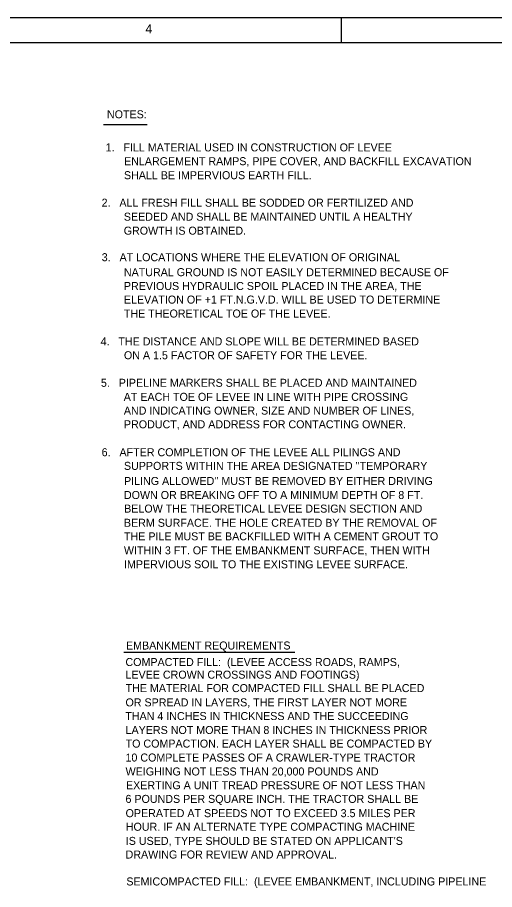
# Model space of a CAD drawing. Extents: x 2127959 to 2137375, y 2146193 to 2153470.
# Drawn here: x 2133592 to 2135661, y 2149692 to 2153470 of the extents above; entities that cross this region are included whole.
import ezdxf

# ---------------------------------------------------------------- set-up
doc = ezdxf.new("R2010")
doc.units = 0
doc.layers.add('Level 1', color=7, linetype='Continuous')

msp = doc.modelspace()

# ---------------------------------------------------------------- linework, layer by layer
at = {"layer": 'Level 1'}
for p, q in [((2134996.845, 2153362.032), (2134996.862, 2153469.881)), ((2128280.166, 2153362.032), (2136678.794, 2153362.027)), ((2133964.481, 2153005.766), (2134154.593, 2153005.766)), ((2134053.658, 2150720.428), (2134795.212, 2150720.428))]:
    msp.add_line(p, q, dxfattribs=at)
msp.add_lwpolyline([(2127959.193, 2153469.025), (2137374.681, 2153469.025), (2137374.681, 2146193.484), (2127959.193, 2146193.484)], close=True, dxfattribs=at)

# ---------------------------------------------------------------- texts
for s, height, p in [('4', 40.073, (2134146.898, 2153400.552)), ('NOTES:', 34.657, (2133980.147, 2153033.079)), ('1.   FILL MATERIAL USED IN CONSTRUCTION OF LEVEE', 34.657, (2133974.327, 2152889.634)), ('ENLARGEMENT RAMPS, PIPE COVER, AND BACKFILL EXCAVATION', 34.657, (2134054.237, 2152829.902)), ('SHALL BE IMPERVIOUS EARTH FILL.', 34.657, (2134053.827, 2152769.252)), ('2.   ALL FRESH FILL SHALL BE SODDED OR FERTILIZED AND', 34.657, (2133956.84, 2152650.108)), ('SEEDED AND SHALL BE MAINTAINED UNTIL A HEALTHY ', 34.657, (2134053.412, 2152589.45)), ('GROWTH IS OBTAINED.', 34.657, (2134052.897, 2152528.985)), ('3.   AT LOCATIONS WHERE THE ELEVATION OF ORIGINAL', 34.657, (2133957.525, 2152414.021)), ('NATURAL GROUND IS NOT EASILY DETERMINED BECAUSE OF', 34.657, (2134053.567, 2152349.091)), ('PREVIOUS HYDRAULIC SPOIL PLACED IN THE AREA, THE ', 34.657, (2134053.618, 2152289.237)), ('ELEVATION OF +1 FT.N.G.V.D. WILL BE USED TO DETERMINE', 34.657, (2134053.633, 2152230.438)), ('THE THEORETICAL TOE OF THE LEVEE.', 34.657, (2134053.182, 2152169.988)), ('4.   THE DISTANCE AND SLOPE WILL BE DETERMINED BASED ', 34.657, (2133952.512, 2152049.325)), ('ON A 1.5 FACTOR OF SAFETY FOR THE LEVEE.', 34.657, (2134053.766, 2151989.3)), ('5.   PIPELINE MARKERS SHALL BE PLACED AND MAINTAINED', 34.657, (2133953.984, 2151870.078)), ('AT EACH TOE OF LEVEE IN LINE WITH PIPE CROSSING', 34.657, (2134052.765, 2151809.183)), ('AND INDICATING OWNER, SIZE AND NUMBER OF LINES,', 34.657, (2134053.344, 2151749.548)), ('PRODUCT, AND ADDRESS FOR CONTACTING OWNER.', 34.657, (2134053.693, 2151690.26)), ('6.   AFTER COMPLETION OF THE LEVEE ALL PILINGS AND', 34.657, (2133957.166, 2151569.249)), ("SUPPORTS WITHIN THE AREA DESIGNATED ''TEMPORARY ", 34.657, (2134053.74, 2151510.22)), ("PILING ALLOWED'' MUST BE REMOVED BY EITHER DRIVING ", 34.657, (2134054.163, 2151444.733)), ('DOWN OR BREAKING OFF TO A MINIMUM DEPTH OF 8 FT.', 34.657, (2134053.764, 2151384.025)), ('BELOW THE THEORETICAL LEVEE DESIGN SECTION AND', 34.657, (2134054.66, 2151325.11)), ('BERM SURFACE. THE HOLE CREATED BY THE REMOVAL OF ', 34.657, (2134053.785, 2151263.717)), ('THE PILE MUST BE BACKFILLED WITH A CEMENT GROUT TO', 34.657, (2134054.14, 2151204.985)), ('WITHIN 3 FT. OF THE EMBANKMENT SURFACE, THEN WITH', 34.657, (2134053.713, 2151144.426)), ('IMPERVIOUS SOIL TO THE EXISTING LEVEE SURFACE.', 34.657, (2134054.163, 2151083.909)), ('EMBANKMENT REQUIREMENTS', 34.657, (2134062.688, 2150732.106)), ('COMPACTED FILL:  (LEVEE ACCESS ROADS, RAMPS, ', 34.657, (2134060.388, 2150660.532)), ('LEVEE CROWN CROSSINGS AND FOOTINGS)', 34.657, (2134060.388, 2150605.875)), ('THE MATERIAL FOR COMPACTED FILL SHALL BE PLACED', 34.657, (2134060.981, 2150547.615)), ('OR SPREAD IN LAYERS, THE FIRST LAYER NOT MORE ', 34.657, (2134060.503, 2150485.758)), ('THAN 4 INCHES IN THICKNESS AND THE SUCCEEDING ', 34.657, (2134059.654, 2150426.546)), ('LAYERS NOT MORE THAN 8 INCHES IN THICKNESS PRIOR', 34.657, (2134060.928, 2150366.066)), ('TO COMPACTION. EACH LAYER SHALL BE COMPACTED BY', 34.657, (2134060.954, 2150307.238)), ('10 COMPLETE PASSES OF A CRAWLER-TYPE TRACTOR', 34.657, (2134060.504, 2150246.851)), ('WEIGHING NOT LESS THAN 20,000 POUNDS AND', 34.657, (2134060.954, 2150186.461)), ('EXERTING A UNIT TREAD PRESSURE OF NOT LESS THAN', 34.657, (2134062.705, 2150126.715)), ('6 POUNDS PER SQUARE INCH. THE TRACTOR SHALL BE', 34.657, (2134060.556, 2150067.631)), ('OPERATED AT SPEEDS NOT TO EXCEED 3.5 MILES PER', 34.657, (2134060.954, 2150005.894)), ('HOUR. IF AN ALTERNATE TYPE COMPACTING MACHINE', 34.657, (2134061.83, 2149947.047)), ("IS USED, TYPE SHOULD BE STATED ON APPLICANT'S", 34.657, (2134061.83, 2149885.786)), ('DRAWING FOR REVIEW AND APPROVAL.', 34.657, (2134060.954, 2149826.809)), ('SEMICOMPACTED FILL:  (LEVEE EMBANKMENT, INCLUDING PIPELINE ', 34.657, (2134064.198, 2149710.048))]:
    msp.add_text(s, height=height, dxfattribs=at).set_placement(p)

doc.saveas('drawing.dxf')
